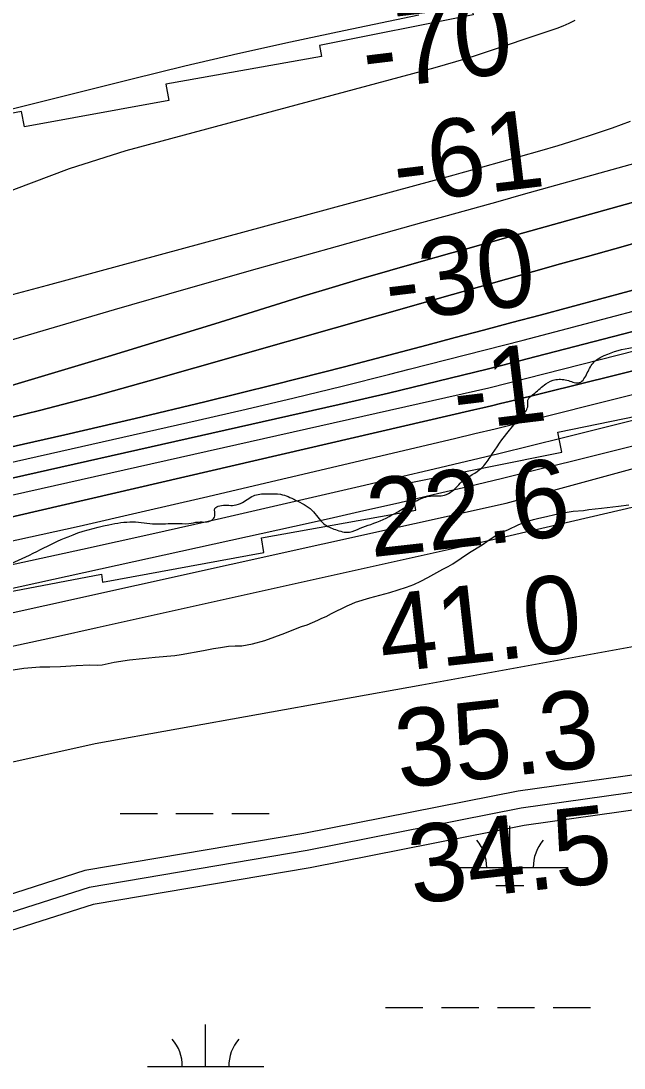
# Model space of a CAD drawing. Extents: x 3281947 to 3319794, y 715894 to 741249.
# Drawn here: x 3302858 to 3303376, y 727498 to 728397 of the extents above; entities that cross this region are included whole.
import ezdxf

# ---------------------------------------------------------------- set-up
doc = ezdxf.new("R2010")
doc.units = 0
for name, color, linetype in [('V-RIVR-EDGE', 7, 'Continuous'), ('V-RIVR-RANG', 7, 'Continuous'), ('V-ROAD-CNTR', 7, 'Continuous'), ('V-RRAP-RVMT', 7, 'Continuous'), ('V-SITE-VEGE', 7, 'Continuous'), ('V-TOPO-DPTH', 7, 'Continuous'), ('V-TOPO-MAJR', 7, 'Continuous'), ('V-TOPO-MINR', 7, 'Continuous'), ('V-TOPO-WATR', 7, 'Continuous'), ('V-WETL-SWMP', 7, 'Continuous')]:
    doc.layers.add(name, color=color, linetype=linetype)

msp = doc.modelspace()

# ---------------------------------------------------------------- linework, layer by layer
at = {"layer": 'V-RIVR-EDGE'}
msp.add_spline([(3301653.45, 727714.35), (3301683.68, 727711.74), (3301710.61, 727709.6), (3301722.63, 727709.57), (3301720.99, 727717.04), (3301721.41, 727719.53), (3301729.29, 727721.16), (3301733.02, 727721.15), (3301733.01, 727717.42), (3301734.25, 727715.35), (3301737.57, 727714.93), (3301747.1, 727715.73), (3301754.98, 727717.37), (3301764.94, 727719.83), (3301783.62, 727731.39), (3301793.16, 727737.17), (3301798.56, 727742.13), (3301810.18, 727745.83), (3301828.01, 727750.35), (3301854.55, 727752.77), (3301881.5, 727756.85), (3301926.69, 727762.54), (3301981.01, 727770.69), (3301997.59, 727771.07), (3302029.1, 727777.21), (3302060.61, 727780.44), (3302081.33, 727779.56), (3302119.46, 727777.4), (3302147.65, 727777.74), (3302187.03, 727780.96), (3302220.62, 727786.27), (3302248.8, 727786.61), (3302265.79, 727784.91), (3302280.3, 727783.63), (3302297.7, 727780.27), (3302314.27, 727778.16), (3302327.12, 727777.3), (3302349.09, 727778.49), (3302363.61, 727783.01), (3302380.61, 727787.11), (3302393.88, 727789.15), (3302410.46, 727791.6), (3302417.93, 727795.31), (3302432.87, 727802.32), (3302442.43, 727810.17), (3302456.54, 727817.6), (3302480.19, 727830.39), (3302498.46, 727840.29), (3302509.25, 727847.73), (3302517.55, 727852.68), (3302533.32, 727860.1), (3302551.99, 727867.1), (3302581.03, 727877.81), (3302610.07, 727889.34), (3302630.4, 727897.16), (3302660.28, 727909.94), (3302690.56, 727922.3), (3302701.76, 727923.51), (3302718.75, 727920.99), (3302742.78, 727918.85), (3302762.25, 727913.83), (3302778, 727912.13), (3302791.26, 727912.1), (3302814.89, 727913.7), (3302822.78, 727918.66), (3302849.75, 727931.02), (3302875.06, 727942.98), (3302898.71, 727954.11), (3302933.56, 727964.39), (3302954.29, 727966.83), (3302973.76, 727965.12), (3302991.17, 727965.49), (3303002.36, 727965.46), (3303010.66, 727966.69), (3303022.27, 727968.32), (3303024.76, 727972.04), (3303024.78, 727978.26), (3303028.93, 727980.73), (3303041.36, 727981.12), (3303048.42, 727983.59), (3303059.21, 727989.78), (3303070.82, 727990.99), (3303081.18, 727990.55), (3303094.01, 727985.55), (3303108.09, 727976.81), (3303118.42, 727965.18), (3303128.35, 727960.18), (3303140.37, 727958.08), (3303149.5, 727961.37), (3303158.62, 727964.66), (3303179.37, 727974.14), (3303198.46, 727985.29), (3303210.08, 727988.99), (3303222.1, 727989.79), (3303228.33, 727993.09), (3303237.88, 728002.18), (3303253.66, 728012.92), (3303261.14, 728022.44), (3303277.78, 728045.61), (3303289, 728058.43), (3303293.58, 728066.71), (3303293.59, 728071.27), (3303299.41, 728077.47), (3303308.96, 728085.32), (3303317.68, 728089.03), (3303328.45, 728088.17), (3303337.98, 728086.49), (3303344.63, 728094.76), (3303350.46, 728104.28), (3303359.18, 728109.65), (3303383.23, 728116.64), (3303397.75, 728118.67), (3303430.93, 728129.37), (3303442.54, 728130.58), (3303454.56, 728130.14), (3303460.78, 728130.95), (3303474.47, 728136.31), (3303501.86, 728150.33), (3303526.34, 728161.46), (3303538.37, 728163.09), (3303555.36, 728163.88), (3303564.48, 728164.68), (3303571.11, 728164.67), (3303588.52, 728162.97), (3303604.68, 728162.51), (3303620.43, 728163.3), (3303641.59, 728168.64), (3303658.17, 728171.91), (3303669.36, 728171.88), (3303681.8, 728171.03), (3303693.82, 728173.9), (3303707.93, 728178.84), (3303720.37, 728181.71), (3303731.56, 728182.51), (3303748.97, 728182.46), (3303763.49, 728186.16), (3303780.07, 728187.78), (3303804.13, 728193.52), (3303820.3, 728198.45), (3303838.97, 728205.04), (3303862.61, 728210.37), (3303887.9, 728214.87), (3303907.38, 728213.99), (3303922.3, 728213.54), (3303943.86, 728215.56), (3303957.54, 728215.94), (3303974.95, 728215.06), (3303996.91, 728212.94), (3304008.11, 728215.4), (3304023.45, 728217.85), (3304030.5, 728219.9), (3304048.74, 728220.27), (3304065.32, 728220.23), (3304092.28, 728229.7)], degree=3, dxfattribs=at)
at = {"layer": 'V-ROAD-CNTR'}
for points in [[(3304438.61, 727882.68), (3304321.76, 727865.94), (3304164.73, 727868.2), (3304030.72, 727835.37), (3303705.25, 727770.19), (3303455.1, 727729.13), (3303290.25, 727705.94), (3303106.68, 727669.71), (3302920.21, 727637.96), (3302849.38, 727615.46), (3302715.94, 727514.18), (3302484.63, 727465.6), (3302360.93, 727417.79), (3302324.11, 727318.18), (3302185.31, 726771.75), (3302145.07, 726494.8)], [(3303450.58, 727758.79), (3303285.25, 727735.54), (3303101.26, 727699.22), (3302913.12, 727667.18), (3302835.37, 727642.49), (3302703.17, 727542.15), (3302476.09, 727494.46), (3302339.79, 727441.78), (3302313.46, 727393.03), (3302155.85, 726777.65), (3302115.38, 726499.12)], [(3303452.84, 727743.96), (3303287.75, 727720.74), (3303103.97, 727684.46), (3302916.66, 727652.57), (3302842.37, 727628.97), (3302709.55, 727528.17), (3302480.36, 727480.03), (3302350.36, 727429.78), (3302327.53, 727387.52), (3302170.58, 726774.7), (3302130.23, 726496.96)]]:
    msp.add_lwpolyline(points, dxfattribs=at)
at = {"layer": 'V-RRAP-RVMT'}
for points in [[(3303513.06, 728496.81), (3303370.85, 728466.33), (3303377.25, 728437.3), (3303245.01, 728409.99), (3303246.58, 728402.37), (3303114.6, 728376.18), (3303116.39, 728366.65), (3302982.56, 728342.88), (3302985.1, 728328.87), (3302861.13, 728306.2), (3302858.76, 728319.32), (3302719.38, 728293.14), (3302722.78, 728274.79), (3302602.65, 728253.37), (3302603.88, 728245.63), (3302475.29, 728219.16), (3302477.56, 728208.67), (3302345.06, 728184.87), (3302347.26, 728172.22), (3302231.5, 728151.19), (3302234.3, 728135.72), (3302082.98, 728106.63)], [(3302028.86, 727749.25), (3302148.57, 727761.46), (3302151.76, 727745.94), (3302300.08, 727774.21), (3302303.58, 727755.01), (3302562.01, 727804.25), (3302559.68, 727816.94), (3302688, 727843.53), (3302683.31, 727866.02), (3302816.53, 727889.97), (3302814.53, 727900.36), (3302927.49, 727921.76), (3302928.17, 727915.1), (3303066.92, 727940.41), (3303064.79, 727953.15), (3303197.23, 727976.84), (3303192.93, 728000.76), (3303322.82, 728026.84), (3303319.43, 728043.79), (3303454.62, 728071.82)]]:
    msp.add_lwpolyline(points, dxfattribs=at)
at = {"layer": 'V-SITE-VEGE'}
for points in [[(3303113.23, 727882.31), (3303116.66, 727884.09), (3303120.29, 727885.66), (3303124.93, 727888.23), (3303138.25, 727894.74), (3303142.28, 727896.31), (3303145.51, 727897.89), (3303157.79, 727901.59), (3303175.1, 727906.26), (3303189.4, 727910.75), (3303195.65, 727913.1), (3303201.7, 727915.86), (3303207.75, 727919.02), (3303220.47, 727926.13), (3303225.11, 727928.5), (3303229.15, 727930.87), (3303243.49, 727940.39), (3303254.2, 727947.12), (3303258.24, 727950.09), (3303264.71, 727954.25), (3303270.96, 727958.01), (3303276.41, 727959.97), (3303285.69, 727964.51), (3303292.54, 727967.06), (3303298.38, 727968.81), (3303303, 727969.97), (3303309.44, 727971.32), (3303316.69, 727973.27), (3303325.54, 727974.99), (3303332.58, 727975.94), (3303341.42, 727976.66), (3303346.05, 727977.42), (3303356.91, 727978.73), (3303371.38, 727980.2), (3303380.23, 727981.33)], [(3302847.94, 727839.11), (3302860.61, 727841), (3302874.48, 727842.28), (3302882.92, 727842.21), (3302892.16, 727842.53), (3302905.62, 727843.41), (3302917.27, 727843.91), (3302923.9, 727843.85), (3302927.92, 727844.01), (3302938.18, 727846.33), (3302951.46, 727848.42), (3302962.51, 727849.32), (3302973.37, 727850.63), (3302990.25, 727852.09), (3302995.68, 727852.84), (3303014.99, 727856.28), (3303023.44, 727858.01), (3303029.68, 727858.96), (3303036.51, 727859.91), (3303042.14, 727860.46), (3303047.96, 727860.4), (3303057.02, 727862.13), (3303067.69, 727865.05), (3303084.81, 727871.12), (3303095.5, 727875.44), (3303099.12, 727876.81), (3303103.96, 727878.38), (3303113.23, 727882.31)]]:
    msp.add_lwpolyline(points, dxfattribs=at)
at = {"layer": 'V-TOPO-DPTH'}
for points in [[(3302841.6, 728081.38), (3302887.42, 728095.14), (3302933.21, 728109), (3302978.96, 728123), (3303024.67, 728137.09), (3303100.64, 728160.65), (3303125.42, 728168.22), (3303150.23, 728175.66), (3303175.1, 728182.89), (3303200.01, 728189.98), (3303228.34, 728197.93), (3303239.12, 728200.95), (3303249.9, 728203.97), (3303260.68, 728206.98), (3303271.46, 728209.99), (3303597.63, 728300.96)], [(3303597.63, 728300.96), (3303271.46, 728209.99), (3303260.68, 728206.98), (3303249.9, 728203.97), (3303239.12, 728200.95), (3303228.34, 728197.93), (3303200.01, 728189.98), (3303175.1, 728182.89), (3303150.23, 728175.66), (3303125.42, 728168.22), (3303100.64, 728160.65), (3303024.67, 728137.09), (3302978.96, 728123), (3302933.21, 728109), (3302887.42, 728095.14), (3302841.6, 728081.38)], [(3302719.16, 727974.74), (3303131.43, 728067.73), (3303152.66, 728072.58), (3303173.89, 728077.51), (3303195.08, 728082.55), (3303216.26, 728087.66), (3303237.41, 728092.87), (3303258.55, 728098.14), (3303279.67, 728103.49), (3303300.77, 728108.91), (3303745.43, 728223.96)], [(3303745.43, 728223.96), (3303300.77, 728108.91), (3303279.67, 728103.49), (3303258.55, 728098.14), (3303237.41, 728092.87), (3303216.26, 728087.66), (3303195.08, 728082.55), (3303173.89, 728077.51), (3303152.66, 728072.58), (3303131.43, 728067.73), (3302719.16, 727974.74)], [(3303391.37, 728207.94), (3303368.14, 728201.45), (3303344.91, 728194.95), (3303321.68, 728188.43), (3303298.46, 728181.89), (3303275.25, 728175.33), (3303252.04, 728168.75), (3303228.84, 728162.16), (3303205.63, 728155.56), (3302968.25, 728087.91), (3302921.28, 728074.97), (3302874.16, 728062.57), (3302826.84, 728050.99)], [(3303391.37, 728207.94), (3303368.14, 728201.45), (3303344.91, 728194.95), (3303321.68, 728188.43), (3303298.46, 728181.89), (3303275.25, 728175.33), (3303252.04, 728168.75), (3303228.84, 728162.16), (3303205.63, 728155.56), (3302968.25, 728087.91), (3302921.28, 728074.97), (3302874.16, 728062.57), (3302826.84, 728050.99)], [(3302095.41, 727816.57), (3302135.84, 727824.41), (3302675.68, 727932.65), (3302683.13, 727934.15), (3302690.58, 727935.68), (3302698.02, 727937.24), (3302705.45, 727938.81), (3302738.22, 727945.82), (3302762.03, 727950.98), (3302785.81, 727956.22), (3302809.57, 727961.58), (3302833.31, 727967.02), (3303247.25, 728063.07), (3303254.82, 728064.84), (3303262.39, 728066.64), (3303269.94, 728068.47), (3303277.49, 728070.33), (3303765.42, 728191.24)], [(3303765.42, 728191.24), (3303277.49, 728070.33), (3303269.94, 728068.47), (3303262.39, 728066.64), (3303254.82, 728064.84), (3303247.25, 728063.07), (3302833.31, 727967.02), (3302809.57, 727961.58), (3302785.81, 727956.22), (3302762.03, 727950.98), (3302738.22, 727945.82), (3302705.45, 727938.81), (3302698.02, 727937.24), (3302690.58, 727935.68), (3302683.13, 727934.15), (3302675.68, 727932.65), (3302135.84, 727824.41), (3302095.41, 727816.57)], [(3303456.93, 728185.64), (3303304.06, 728144.53), (3303279.77, 728138.02), (3303255.47, 728131.54), (3303231.15, 728125.11), (3303206.83, 728118.72), (3303136, 728100.16), (3303076.18, 728084.81), (3303016.26, 728069.87), (3302956.18, 728055.56), (3302896.01, 728041.65), (3302740.97, 728006.67)], [(3302740.97, 728006.67), (3302896.01, 728041.65), (3302956.18, 728055.56), (3303016.26, 728069.87), (3303076.18, 728084.81), (3303136, 728100.16), (3303206.83, 728118.72), (3303231.15, 728125.11), (3303255.47, 728131.54), (3303279.77, 728138.02), (3303304.06, 728144.53), (3303456.93, 728185.64)], [(3301933.96, 727764.56), (3302172.49, 727801.07), (3302260.31, 727815.1), (3302347.99, 727829.89), (3302435.48, 727845.81), (3302522.83, 727862.5), (3302643.94, 727886.44), (3302670.62, 727891.8), (3302697.28, 727897.25), (3302723.9, 727902.86), (3302750.51, 727908.57), (3302911, 727943.5), (3302970.72, 727956.66), (3303030.4, 727970), (3303090, 727983.64), (3303149.57, 727997.48), (3303212.99, 728012.38), (3303240.8, 728018.98), (3303268.58, 728025.65), (3303296.34, 728032.45), (3303324.08, 728039.32), (3303784.38, 728154.51)]]:
    msp.add_lwpolyline(points, dxfattribs=at)
at = {"layer": 'V-TOPO-MAJR'}
for points in [[(3301938.34, 727941.03), (3302487.35, 728031.21), (3302518.41, 728036.66), (3302549.38, 728042.56), (3302580.22, 728049.12), (3302610.96, 728056.13), (3302641.58, 728063.72), (3302672.11, 728071.62), (3302702.51, 728080), (3302732.82, 728088.69), (3302877.25, 728131.35), (3302938.6, 728149.31), (3303000.01, 728167.08), (3303061.51, 728184.56), (3303123.05, 728201.84), (3303202.62, 728223.97), (3303224.43, 728230.04), (3303246.23, 728236.12), (3303268.03, 728242.2), (3303289.83, 728248.29), (3303457.48, 728295.14)], [(3302087.62, 727731.41), (3302687.52, 727827.95), (3302697.87, 727829.68), (3302708.21, 727831.48), (3302718.53, 727833.4), (3302728.84, 727835.4), (3302780.17, 727845.67), (3302816.11, 727852.97), (3302852.01, 727860.44), (3302887.87, 727868.14), (3302923.69, 727876), (3303250.75, 727948.89), (3303264.49, 727951.97), (3303278.23, 727955.09), (3303291.96, 727958.24), (3303305.68, 727961.42), (3303439.71, 727992.67)]]:
    msp.add_lwpolyline(points, dxfattribs=at)
at = {"layer": 'V-TOPO-MINR'}
for points in [[(3303199.93, 728402.08), (3303135.42, 728388.78), (3303089.84, 728379.08), (3303044.35, 728369), (3302998.99, 728358.35), (3302953.71, 728347.32), (3302719.05, 728288.58), (3302681.19, 728279.6), (3302643.2, 728271.25), (3302605.02, 728263.84), (3302566.7, 728257.05), (3302530.09, 728251.04), (3302473.3, 728242.3), (3302416.4, 728234.34), (3302359.36, 728227.54), (3302302.21, 728221.53), (3301857.16, 728179.27)], [(3302020.39, 728013.24), (3302658.05, 728147.39), (3302659.34, 728147.68), (3302662.37, 728148.43), (3302665.8, 728149.41), (3302668.43, 728150.23), (3302670.85, 728151.08), (3302673.21, 728152.05), (3302675.49, 728153.19), (3302677.72, 728154.44), (3302761.27, 728205.44), (3302806.11, 728230.23), (3302852.11, 728252.35), (3302899.82, 728270.45), (3302948.69, 728285.87), (3303214, 728357.21), (3303222.92, 728359.7), (3303231.82, 728362.29), (3303240.66, 728365.03), (3303249.48, 728367.88), (3303318.64, 728390.92), (3303323.96, 728392.93), (3303329.15, 728395.23), (3303334.14, 728397.93)], [(3302046.24, 727794.29), (3302122.29, 727806.58), (3302198.23, 727819.51), (3302274, 727833.43), (3302349.66, 727847.99), (3302660.01, 727909.79), (3302676.95, 727913.21), (3302693.89, 727916.68), (3302710.81, 727920.23), (3302727.72, 727923.84), (3302801.06, 727939.66), (3302854.6, 727951.36), (3302908.09, 727963.25), (3302961.52, 727975.44), (3303014.9, 727987.83), (3303230.67, 728038.51), (3303248.03, 728042.63), (3303265.38, 728046.8), (3303282.72, 728051.05), (3303300.03, 728055.36), (3304370.87, 728324.16)], [(3301244.78, 727669.43), (3301836.26, 727728.43), (3301867.59, 727731.78), (3301898.88, 727735.44), (3301930.11, 727739.56), (3301961.3, 727743.97), (3302654.09, 727847.24), (3302662.52, 727848.55), (3302670.93, 727849.94), (3302679.32, 727851.44), (3302687.7, 727853.01), (3302696.07, 727854.67), (3302704.42, 727856.38), (3302712.76, 727858.15), (3302721.09, 727859.97), (3303275.06, 727983.01), (3304462.34, 728306.83)], [(3302837.81, 728158.65), (3302880.97, 728170.25), (3302924.12, 728181.93), (3303230.29, 728265.13), (3303236.42, 728266.8), (3303242.54, 728268.49), (3303248.66, 728270.18), (3303254.78, 728271.89), (3303303.75, 728285.61), (3303319.48, 728290.19), (3303335.15, 728294.98), (3303350.71, 728300.08), (3303366.2, 728305.39), (3303381.59, 728311.01)], [(3302841.6, 728081.38), (3302887.42, 728095.14), (3302933.21, 728109), (3302978.96, 728123), (3303024.67, 728137.09), (3303100.64, 728160.65), (3303125.42, 728168.22), (3303150.23, 728175.66), (3303175.1, 728182.89), (3303200.01, 728189.98), (3303228.34, 728197.93), (3303239.12, 728200.95), (3303249.9, 728203.97), (3303260.68, 728206.98), (3303271.46, 728209.99), (3303597.63, 728300.96)], [(3301930.61, 727801.59), (3302162.34, 727848.08), (3302246.4, 727864.94), (3302330.45, 727881.8), (3302414.52, 727898.65), (3302498.58, 727915.5), (3302661.52, 727948.15), (3302664.11, 727948.66), (3302666.7, 727949.18), (3302669.29, 727949.69), (3302671.88, 727950.2), (3302674.47, 727950.72), (3302677.06, 727951.24), (3302679.65, 727951.76), (3302682.24, 727952.3), (3302682.44, 727952.34), (3302685.13, 727952.91), (3302687.81, 727953.49), (3302690.49, 727954.07), (3302693.17, 727954.67), (3303260.07, 728081.96), (3304003.56, 728271.3)], [(3302719.16, 727974.74), (3303131.43, 728067.73), (3303152.66, 728072.58), (3303173.89, 728077.51), (3303195.08, 728082.55), (3303216.26, 728087.66), (3303237.41, 728092.87), (3303258.55, 728098.14), (3303279.67, 728103.49), (3303300.77, 728108.91), (3303745.43, 728223.96)], [(3302826.84, 728050.99), (3302874.16, 728062.57), (3302921.28, 728074.97), (3302968.25, 728087.91), (3303205.63, 728155.56), (3303228.84, 728162.16), (3303252.04, 728168.75), (3303275.25, 728175.33), (3303298.46, 728181.89), (3303321.68, 728188.43), (3303344.91, 728194.95), (3303368.14, 728201.45), (3303391.37, 728207.94)], [(3302740.97, 728006.67), (3302896.01, 728041.65), (3302956.18, 728055.56), (3303016.26, 728069.87), (3303076.18, 728084.81), (3303136, 728100.16), (3303206.83, 728118.72), (3303231.15, 728125.11), (3303255.47, 728131.54), (3303279.77, 728138.02), (3303304.06, 728144.53), (3303456.93, 728185.64)], [(3302745.14, 727994.37), (3303010.44, 728054.31), (3303051.67, 728063.79), (3303092.86, 728073.48), (3303133.97, 728083.49), (3303175.02, 728093.7), (3303191.72, 728097.92), (3303224.38, 728106.23), (3303257.02, 728114.6), (3303289.64, 728123.07), (3303322.24, 728131.61), (3303539.11, 728188.76)], [(3301933.96, 727764.56), (3302172.49, 727801.07), (3302260.31, 727815.1), (3302347.99, 727829.89), (3302435.48, 727845.81), (3302522.83, 727862.5), (3302643.94, 727886.44), (3302670.62, 727891.8), (3302697.28, 727897.25), (3302723.9, 727902.86), (3302750.51, 727908.57), (3302911, 727943.5), (3302970.72, 727956.66), (3303030.4, 727970), (3303090, 727983.64), (3303149.57, 727997.48), (3303212.99, 728012.38), (3303240.8, 728018.98), (3303268.58, 728025.65), (3303296.34, 728032.45), (3303324.08, 728039.32), (3303784.38, 728154.51)], [(3301947.63, 727754.29), (3302407, 727823.71), (3302456.17, 727831.47), (3302505.26, 727839.66), (3302554.24, 727848.5), (3302603.14, 727857.76), (3302627.44, 727862.53), (3302664.11, 727869.86), (3302700.75, 727877.35), (3302737.33, 727885.08), (3302773.88, 727892.99), (3303093.07, 727963.14), (3303122.92, 727969.76), (3303152.75, 727976.48), (3303182.54, 727983.32), (3303212.32, 727990.25), (3303242.07, 727997.3), (3303271.8, 728004.43), (3303301.49, 728011.69), (3303331.17, 728019.03), (3303457.85, 728050.64)]]:
    msp.add_lwpolyline(points, dxfattribs=at)
at = {"layer": 'V-TOPO-WATR'}
msp.add_lwpolyline([(3302095.41, 727816.57), (3302135.84, 727824.41), (3302675.68, 727932.65), (3302683.13, 727934.15), (3302690.58, 727935.68), (3302698.02, 727937.24), (3302705.45, 727938.81), (3302738.22, 727945.82), (3302762.03, 727950.98), (3302785.81, 727956.22), (3302809.57, 727961.58), (3302833.31, 727967.02), (3303247.25, 728063.07), (3303254.82, 728064.84), (3303262.39, 728066.64), (3303269.94, 728068.47), (3303277.49, 728070.33), (3303765.42, 728191.24)], dxfattribs=at)
at = {"layer": 'V-WETL-SWMP'}
for p, q in [((3302943.35, 727716.17), (3302975.35, 727716.17)), ((3302991.35, 727716.17), (3303023.35, 727716.17)), ((3303039.35, 727716.17), (3303071.35, 727716.17)), ((3303278.2, 727669.74), (3303278.2, 727705.74)), ((3303228.2, 727669.74), (3303328.2, 727669.74)), ((3303266.2, 727654.3), (3303290.2, 727654.3)), ((3303171.35, 727549.66), (3303203.35, 727549.66)), ((3303219.35, 727549.66), (3303251.35, 727549.66)), ((3303267.35, 727549.66), (3303299.35, 727549.66)), ((3303315.35, 727549.66), (3303347.35, 727549.66)), ((3303016.76, 727498.92), (3303016.76, 727534.92)), ((3302966.76, 727498.92), (3303066.76, 727498.92))]:
    msp.add_line(p, q, dxfattribs=at)
msp.add_lwpolyline([(3303423.06, 727866.51), (3303202.6, 727826.39), (3302922.02, 727776.25), (3302380.91, 727655.91), (3302230.6, 727575.68), (3301990.1, 727535.56), (3301869.85, 727525.53), (3301739.59, 727525.53), (3301489.07, 727535.56), (3301108.29, 727535.56)], dxfattribs=at)
for centre, start, end in [((3303222.96, 727670.21), 359.22818, 40.77184), ((3303333.44, 727670.21), 139.22818, 180.77184), ((3302961.52, 727499.4), 359.22818, 40.77184), ((3303072.01, 727499.4), 139.22818, 180.77184)]:
    msp.add_arc(centre, 35.25, start, end, dxfattribs=at)

# ---------------------------------------------------------------- texts
at = {"layer": 'V-RIVR-RANG'}
for s, rotation, p in [('-70', 6.90386, (3303154.74, 728337.61)), ('-61', 6.90386, (3303181.24, 728240.09)), ('-30', 6.90386, (3303174.23, 728138.51)), ('-1', 6.90386, (3303232.68, 728044.86)), ('22.6', 6.35833, (3303158.96, 727936.36)), ('41.0', 6.35833, (3303169.22, 727836.89)), ('35.3', 6.35833, (3303183.42, 727737.85)), ('34.5', 6.35833, (3303194.74, 727638.5))]:
    msp.add_text(s, height=67, rotation=rotation, dxfattribs=at).set_placement(p)

doc.saveas('drawing.dxf')
